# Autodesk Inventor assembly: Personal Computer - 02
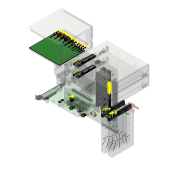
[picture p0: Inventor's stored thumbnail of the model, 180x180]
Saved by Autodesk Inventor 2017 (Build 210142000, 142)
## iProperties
Company: Autodesk Inc.
Created: 2016-11
Part Number: Personal Computer - 02
Document SubType Name: Assembly
Designer: DanielSeverino
Sending System: Autodesk Inventor 2017
Preprocessor: ST-DEVELOPER v16.5
Title: C:\Users\DanielSeverino\Documents\Daniel Severino\00 - YouTube\Peças Inventor YouTube\Personal Computer - Modificado\Aulas Daniel.CAD\Aula 06\Personal Computer - 02.stp
Author: DanielSeverino
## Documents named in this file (13)
- C:\Users\DanielSeverino\Desktop\01\Personal Computer - 02.iam
- C:\Users\DanielSeverino\Desktop\01\LED Button.ipt
- C:\Users\DanielSeverino\Desktop\01\Power Supply.iam
- C:\Users\DanielSeverino\Desktop\01\Motherboard.iam
- C:\Users\DanielSeverino\Desktop\01\Graphics Card.iam
- C:\Users\DanielSeverino\Desktop\01\CDROM.ipt
- C:\Users\DanielSeverino\Desktop\01\Hard Drive.ipt
- C:\Users\DanielSeverino\Desktop\01\CD Ribbon Cable.iam
- C:\Users\DanielSeverino\Desktop\01\Power Supply Harness.iam
- C:\Users\DanielSeverino\Desktop\01\Cooling Fan Harness.iam
- C:\Users\DanielSeverino\Desktop\01\Processor Fan Harness.iam
- C:\Users\DanielSeverino\Desktop\01\Front Panel Harness.iam
- C:\Users\DanielSeverino\Desktop\01\HD Ribbon Cable.iam
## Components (14 placed, 12 different names)
1. LED Button:1
2. Power Supply:1 [sub-assembly]
3. Motherboard:1 [sub-assembly]
4. Graphics Card:1 [sub-assembly]
5. CDROM:1
6. CDROM:2
7. Hard Drive:1
8. Hard Drive:2
9. CD Ribbon Cable [sub-assembly]
10. Power Supply Harness [sub-assembly]
11. Cooling Fan Harness [sub-assembly]
12. Processor Fan Harness [sub-assembly]
13. Front Panel Harness [sub-assembly]
14. HD Ribbon Cable [sub-assembly]
